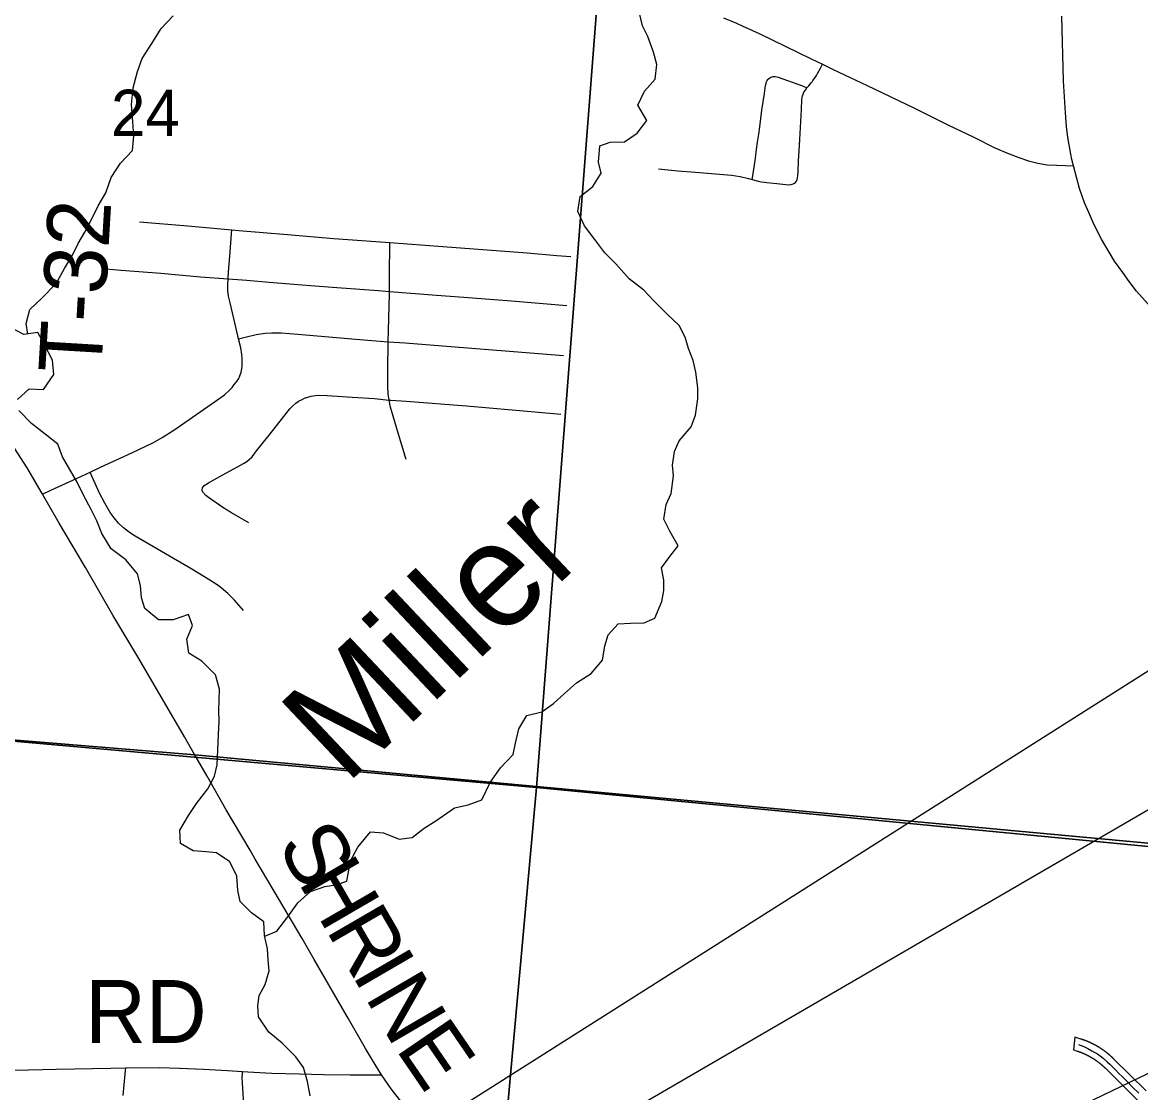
# Model space of a CAD drawing. Extents: x 0 to 34, y 0 to 22.
# Drawn here: x 5.803 to 6.814, y 18.991 to 19.958 of the extents above; entities that cross this region are included whole.
import ezdxf

# ---------------------------------------------------------------- set-up
doc = ezdxf.new("R2010")
doc.units = 0
for name, color, linetype in [('GM_X_City_Street', 7, 'Continuous'), ('GM_X_County_Road', 7, 'Continuous'), ('GM_X_County_Road_Text', 7, 'Continuous'), ('GM_X_Minor_River', 7, 'Continuous'), ('GM_X_Minor_River_Text', 7, 'Continuous'), ('GM_X_Section', 7, 'Continuous'), ('GM_X_Section_Text', 7, 'Continuous'), ('GM_X_State_Route', 7, 'Continuous'), ('GM_X_Township_Road', 7, 'Continuous'), ('GM_X_Township_Road_Text', 7, 'Continuous'), ('SC_Shading1', 7, 'Continuous'), ('SH_Text', 7, 'Continuous')]:
    doc.layers.add(name, color=color, linetype=linetype)

msp = doc.modelspace()

# ---------------------------------------------------------------- linework, layer by layer
at = {"layer": 'GM_X_City_Street'}
for points in [[(3.2709, 19.533), (4.2098, 19.4463), (4.8058, 19.3935), (5.2204, 19.3568), (5.9589, 19.2964), (6.8431, 19.2142)], [(6.8431, 19.2142), (5.9589, 19.2964), (5.2204, 19.3568), (5.2191, 19.3417), (5.2164, 19.3114), (5.2133, 19.2734), (5.2108, 19.2453), (5.2093, 19.2272), (5.2077, 19.2098), (5.2042, 19.1724), (5.2034, 19.1643), (5.2004, 19.1272), (5.1954, 19.0684), (5.1927, 19.0376), (5.1894, 18.9945), (5.185, 18.9419)]]:
    msp.add_lwpolyline(points, dxfattribs=at)
at = {"layer": 'GM_X_County_Road'}
for points in [[(5.8211, 19.5319), (5.8207, 19.5326), (5.8071, 19.5556), (5.793, 19.5776), (5.7836, 19.5916), (5.7767, 19.6008), (5.7707, 19.6081)], [(5.9586, 19.2967), (5.9495, 19.3125), (5.9083, 19.3835), (5.8848, 19.4226), (5.86, 19.4657), (5.8362, 19.5057), (5.8211, 19.5319)], [(6.1275, 19.0072), (6.1195, 19.0202), (6.1132, 19.0309), (6.0976, 19.0577), (6.0667, 19.1114), (6.0558, 19.1302), (6.0306, 19.1731), (6.0133, 19.202), (6.0087, 19.21), (5.9872, 19.2467), (5.9699, 19.2771), (5.9591, 19.2958), (5.9586, 19.2967)], [(6.2507, 18.8942), (6.2289, 18.9088), (6.2115, 18.9212), (6.2062, 18.9247), (6.2013, 18.9285), (6.1917, 18.9363), (6.1799, 18.9464), (6.1731, 18.9527), (6.162, 18.9634), (6.1536, 18.9725), (6.1458, 18.9821), (6.1364, 18.9944), (6.1275, 19.0072)]]:
    msp.add_lwpolyline(points, dxfattribs=at)
at = {"layer": 'GM_X_Minor_River'}
for points in [[(6.1768, 19.2366), (6.1935, 19.2484), (6.206, 19.251), (6.2181, 19.2555), (6.2258, 19.2714), (6.235, 19.2846), (6.2465, 19.2966), (6.2488, 19.3069), (6.2516, 19.3198), (6.2588, 19.3319), (6.2725, 19.3352), (6.2831, 19.3427), (6.293, 19.3517), (6.3037, 19.3615), (6.317, 19.3698), (6.3273, 19.3818), (6.3293, 19.3947), (6.3324, 19.4046), (6.3416, 19.4148), (6.3525, 19.4154), (6.365, 19.4157), (6.3745, 19.4198), (6.3811, 19.435), (6.3827, 19.4448), (6.3827, 19.4543), (6.3806, 19.4653), (6.3882, 19.4755), (6.3958, 19.4853), (6.3884, 19.4979), (6.3828, 19.5093), (6.3848, 19.5226), (6.3894, 19.5324), (6.3914, 19.5484), (6.3907, 19.5582), (6.3923, 19.5704), (6.3966, 19.5802), (6.4076, 19.5926), (6.4115, 19.6032), (6.4135, 19.618), (6.4136, 19.6279), (6.4118, 19.642), (6.4092, 19.6526), (6.4052, 19.6636), (6.4022, 19.6739), (6.3966, 19.6842), (6.3857, 19.6945), (6.3737, 19.7067), (6.3647, 19.7163), (6.3515, 19.7266), (6.3395, 19.74), (6.3294, 19.7499), (6.3204, 19.7621), (6.3111, 19.7744), (6.3051, 19.7873), (6.3071, 19.8009), (6.3185, 19.81), (6.3262, 19.8221), (6.3236, 19.8319), (6.3249, 19.8467), (6.3343, 19.8501), (6.3472, 19.8503), (6.3586, 19.8582), (6.3674, 19.8696), (6.3592, 19.8836), (6.3653, 19.8961), (6.3749, 19.9071), (6.3765, 19.9203), (6.3735, 19.9313), (6.3684, 19.9454), (6.3635, 19.9553), (6.3606, 19.9679)], [(5.8078, 19.6766), (5.8063, 19.686), (5.8095, 19.6989), (5.8206, 19.709), (5.8333, 19.7222), (5.8411, 19.7358), (5.8485, 19.7486), (5.8532, 19.7584), (5.8594, 19.7686), (5.8648, 19.7788), (5.8714, 19.7924), (5.8784, 19.8041), (5.8831, 19.8181), (5.8917, 19.8309), (5.9024, 19.8426), (5.9037, 19.8558), (5.9028, 19.8684), (5.9014, 19.884), (5.9031, 19.8992), (5.9071, 19.9139), (5.9111, 19.9257), (5.92, 19.9392), (5.9285, 19.9528), (5.9393, 19.9641)], [(5.7986, 19.6173), (5.809, 19.6271), (5.8219, 19.6265), (5.8312, 19.6401), (5.8302, 19.653), (5.8224, 19.668), (5.8168, 19.6779), (5.8043, 19.6762), (5.7914, 19.6828)], [(5.9107, 19.4381), (5.9097, 19.4492), (5.9071, 19.4598), (5.8963, 19.4725), (5.8831, 19.4826), (5.8746, 19.4963), (5.8701, 19.5078), (5.8653, 19.5173), (5.8579, 19.5315), (5.8523, 19.5426), (5.8457, 19.5541), (5.8393, 19.5655), (5.8349, 19.577), (5.8236, 19.5862), (5.8112, 19.5959), (5.7996, 19.6074)], [(6.063, 18.9881), (6.0605, 19.0011), (6.0569, 19.0137), (6.0501, 19.0233), (6.0378, 19.0356), (6.0257, 19.0456), (6.0164, 19.0594), (6.0158, 19.0693), (6.017, 19.0788), (6.0225, 19.0886), (6.0261, 19.1011), (6.025, 19.111), (6.0244, 19.1209), (6.0219, 19.1331), (6.0213, 19.1453), (6.01, 19.1534), (5.9999, 19.1638), (5.9977, 19.1737), (5.9968, 19.1866), (5.9905, 19.1996), (5.9784, 19.2077), (5.9689, 19.2086), (5.9572, 19.2095), (5.9458, 19.2161), (5.9452, 19.2283), (5.953, 19.2415), (5.9604, 19.2524), (5.9704, 19.2656), (5.9766, 19.277), (5.979, 19.2872), (5.9801, 19.3145), (5.9807, 19.3267), (5.9804, 19.3362), (5.9809, 19.3461), (5.981, 19.3556), (5.9774, 19.3686), (5.965, 19.3809), (5.9533, 19.3882), (5.9516, 19.4008), (5.9567, 19.4133), (5.953, 19.4232), (5.9393, 19.4184), (5.926, 19.4182), (5.9136, 19.4286), (5.9107, 19.4381)], [(6.0221, 19.1324), (6.033, 19.1368), (6.043, 19.15), (6.0519, 19.1624), (6.0634, 19.1729), (6.0764, 19.1773), (6.0867, 19.1787), (6.0962, 19.182), (6.0995, 19.2006), (6.1061, 19.2127), (6.1177, 19.2266), (6.1294, 19.2257), (6.1434, 19.2202), (6.1552, 19.2216), (6.166, 19.2299), (6.1768, 19.2366)]]:
    msp.add_lwpolyline(points, dxfattribs=at)
at = {"layer": 'GM_X_Section'}
for points in [[(5.3135, 20.3557), (6.3446, 20.2616), (6.2677, 19.2667), (5.2197, 19.3596)], [(7.3544, 20.1697), (7.2676, 19.1705), (6.2677, 19.2667), (6.3446, 20.2616)], [(5.2197, 19.3596), (6.2677, 19.2667), (6.1771, 18.2641), (5.133, 18.3597)], [(6.2677, 19.2667), (7.2676, 19.1705), (7.1751, 18.1682), (6.1771, 18.2641)]]:
    msp.add_lwpolyline(points, close=True, dxfattribs=at)
at = {"layer": 'GM_X_State_Route'}
for points in [[(6.7517, 19.8344), (6.7506, 19.8393), (6.7481, 19.8543), (6.7468, 19.8641), (6.7458, 19.8766), (6.744, 19.9054), (6.7427, 19.9639)], [(6.9759, 19.5828), (6.9726, 19.5851), (6.9399, 19.6089), (6.8982, 19.64), (6.871, 19.6605), (6.8564, 19.6714), (6.8421, 19.6832), (6.8319, 19.6924), (6.8206, 19.7035), (6.8102, 19.7153), (6.8033, 19.7242), (6.7976, 19.7323), (6.7903, 19.7426), (6.7853, 19.7506), (6.7785, 19.7623), (6.7714, 19.7759), (6.7669, 19.7865), (6.7632, 19.7952), (6.7586, 19.8083), (6.7531, 19.8286), (6.7517, 19.8344)]]:
    msp.add_lwpolyline(points, dxfattribs=at)
at = {"layer": 'GM_X_Township_Road'}
for points in [[(6.4366, 19.9625), (6.4484, 19.9576), (6.4537, 19.9553), (6.469, 19.9482), (6.516, 19.9254), (6.5262, 19.9204)], [(6.5122, 19.899), (6.5139, 19.901), (6.516, 19.9036), (6.5169, 19.9046), (6.5176, 19.9057), (6.5195, 19.9084), (6.5207, 19.9104), (6.5218, 19.9121), (6.5243, 19.9169), (6.5262, 19.9204)], [(6.5262, 19.9204), (6.5359, 19.9157), (6.5666, 19.9012), (6.6087, 19.881), (6.6401, 19.8655), (6.6631, 19.8545), (6.682, 19.845)], [(6.4626, 19.8164), (6.4631, 19.8197), (6.4643, 19.8274), (6.4655, 19.8356), (6.4666, 19.8435), (6.4675, 19.85), (6.4686, 19.8573), (6.4695, 19.864), (6.4715, 19.8791), (6.4738, 19.894), (6.4748, 19.9013), (6.4752, 19.903), (6.4754, 19.9041), (6.4758, 19.9052), (6.4763, 19.9059), (6.4768, 19.9066), (6.4774, 19.9073), (6.4786, 19.9082), (6.4799, 19.9089), (6.4816, 19.9093), (6.4833, 19.9094), (6.4848, 19.9092), (6.4862, 19.9089), (6.5082, 19.9008), (6.5122, 19.899)], [(6.4626, 19.8164), (6.468, 19.8149), (6.4711, 19.8141), (6.4758, 19.8135), (6.4849, 19.8126), (6.4957, 19.8116), (6.4978, 19.8118), (6.4997, 19.8123), (6.501, 19.8129), (6.5019, 19.8136), (6.5027, 19.8148), (6.5032, 19.8162), (6.5036, 19.8178), (6.5038, 19.8196), (6.5041, 19.8235), (6.5046, 19.8331), (6.5051, 19.8422), (6.5056, 19.8525), (6.5072, 19.8797), (6.5076, 19.8885), (6.5078, 19.8903), (6.508, 19.8919), (6.5086, 19.8935), (6.5093, 19.8951), (6.5107, 19.8971), (6.5122, 19.899)], [(6.682, 19.845), (6.6949, 19.8394), (6.7036, 19.8361), (6.7124, 19.8332), (6.721, 19.8309), (6.7292, 19.8296), (6.738, 19.8291), (6.7531, 19.8286)], [(6.3779, 19.826), (6.3955, 19.8242), (6.4115, 19.8228), (6.4438, 19.8201), (6.4518, 19.8191), (6.4594, 19.8173), (6.4626, 19.8164)], [(5.9087, 19.7781), (5.9524, 19.7743), (5.9922, 19.7707)], [(5.9888, 19.7264), (5.9893, 19.7328), (5.9904, 19.747), (5.9919, 19.7672), (5.9922, 19.7707)], [(5.9922, 19.7707), (5.9985, 19.7702), (6.0426, 19.7666), (6.0846, 19.7631), (6.135, 19.7592)], [(6.1349, 19.715), (6.1349, 19.7326), (6.135, 19.7557), (6.135, 19.7592)], [(6.135, 19.7592), (6.1829, 19.7557), (6.211, 19.7536), (6.2592, 19.75), (6.286, 19.7475), (6.2986, 19.7466)], [(5.8782, 19.7354), (5.8921, 19.7342), (5.9281, 19.7315), (5.964, 19.7283), (5.9888, 19.7264)], [(5.9984, 19.6722), (5.9963, 19.6816), (5.9906, 19.7047), (5.9893, 19.7108), (5.9885, 19.716), (5.9885, 19.7211), (5.9888, 19.7264)], [(5.9888, 19.7264), (6.0059, 19.7252), (6.0259, 19.7236), (6.0484, 19.7218), (6.0635, 19.7206), (6.0873, 19.7188), (6.1247, 19.7159), (6.1349, 19.715)], [(6.1335, 19.6697), (6.1339, 19.6799), (6.1347, 19.7126), (6.1349, 19.715)], [(6.1349, 19.715), (6.1772, 19.7116), (6.2021, 19.7098), (6.245, 19.7065), (6.2952, 19.7024)], [(5.9984, 19.6722), (6.0044, 19.6737), (6.0142, 19.6761), (6.0223, 19.6775), (6.0283, 19.6778), (6.0369, 19.6776), (6.0518, 19.6766), (6.1043, 19.672), (6.1335, 19.6697)], [(5.8642, 19.5518), (5.8736, 19.5563), (5.9017, 19.5692), (5.9214, 19.5785), (5.9294, 19.583), (5.9399, 19.5897), (5.9805, 19.6179), (5.9855, 19.6217), (5.9901, 19.626), (5.9924, 19.6282), (5.9945, 19.6309), (5.9965, 19.6333), (5.9985, 19.6363), (5.9996, 19.6389), (6.0008, 19.642), (6.0014, 19.6451), (6.0016, 19.6479), (6.0016, 19.6515), (6.0016, 19.6545), (6.0013, 19.6581), (6.0003, 19.664), (5.9984, 19.6722)], [(6.1344, 19.6169), (6.1335, 19.6227), (6.1332, 19.6294), (6.1332, 19.644), (6.1335, 19.6697)], [(6.1335, 19.6697), (6.149, 19.6686), (6.1977, 19.6648), (6.2507, 19.6604), (6.2921, 19.6571)], [(6.0075, 19.5061), (5.992, 19.515), (5.984, 19.5199), (5.9712, 19.5289), (5.9686, 19.5308), (5.9659, 19.5338), (5.9655, 19.5353), (5.9658, 19.5375), (5.9673, 19.5398), (5.9711, 19.5422), (5.9835, 19.549), (5.9973, 19.5567), (6.0027, 19.5596), (6.0059, 19.5614), (6.0082, 19.5634), (6.0105, 19.5657), (6.0146, 19.571), (6.0259, 19.5851), (6.038, 19.6007), (6.0446, 19.6089), (6.0474, 19.6118), (6.0502, 19.6141), (6.0526, 19.6158), (6.0551, 19.6172), (6.0579, 19.6185), (6.061, 19.6197), (6.0641, 19.6204), (6.0676, 19.621), (6.0707, 19.6213), (6.0784, 19.6212), (6.1009, 19.6195), (6.1211, 19.6182), (6.1344, 19.6169)], [(6.1344, 19.6169), (6.1361, 19.6168), (6.1498, 19.6159), (6.2044, 19.6117), (6.2661, 19.6062), (6.2898, 19.6043)], [(6.1498, 19.5632), (6.1419, 19.589), (6.1357, 19.6105), (6.1344, 19.6169)], [(5.8211, 19.5319), (5.8287, 19.5354), (5.8484, 19.5444), (5.8642, 19.5518)], [(6.0029, 19.4267), (5.9946, 19.4361), (5.9885, 19.4421), (5.9808, 19.4486), (5.9724, 19.4542), (5.9562, 19.464), (5.9049, 19.494), (5.8998, 19.4973), (5.8942, 19.5014), (5.8898, 19.5057), (5.8858, 19.5104), (5.8822, 19.5154), (5.8774, 19.5238), (5.873, 19.5321), (5.8658, 19.5481), (5.8642, 19.5518)], [(6.7576, 19.0346), (6.7624, 19.0326), (6.7661, 19.0308), (6.7696, 19.0289), (6.7724, 19.0273), (6.7747, 19.026), (6.7773, 19.0242), (6.78, 19.0221), (6.7837, 19.0189), (6.786, 19.0168), (6.7885, 19.0142), (6.7914, 19.0112), (6.7942, 19.0084), (6.7973, 19.0052), (6.801, 19.0015), (6.8064, 18.996), (6.8121, 18.9906)], [(5.7589, 19.0107), (5.7774, 19.011), (5.796, 19.0114), (5.8333, 19.0121), (5.883, 19.0132), (5.896, 19.0133)], [(5.896, 19.0133), (5.8958, 19.0111), (5.8938, 18.9885)], [(5.896, 19.0133), (5.9264, 19.0137), (5.945, 19.0132), (5.9666, 19.0123), (5.9882, 19.011), (6.0018, 19.0101), (6.0068, 19.0098), (6.0285, 19.0087), (6.0534, 19.0079), (6.0751, 19.0074), (6.0993, 19.0072), (6.1235, 19.0072), (6.1275, 19.0072)], [(6.0033, 18.9752), (6.0018, 18.9997), (6.0017, 19.0046), (6.0018, 19.0087), (6.0018, 19.0101)]]:
    msp.add_lwpolyline(points, dxfattribs=at)
at = {"layer": 'SC_Shading1'}
msp.add_lwpolyline([(6.8188, 18.9925), (6.804, 19.0072), (6.7896, 19.0213), (6.7897, 19.0213), (6.7895, 19.0214), (6.7894, 19.0216), (6.7893, 19.0217), (6.7891, 19.0218), (6.789, 19.022), (6.7889, 19.0221), (6.7888, 19.0222), (6.7886, 19.0223), (6.7885, 19.0225), (6.7884, 19.0226), (6.7882, 19.0227), (6.7881, 19.0228), (6.788, 19.0229), (6.7878, 19.0231), (6.7877, 19.0232), (6.7876, 19.0233), (6.7874, 19.0234), (6.7873, 19.0236), (6.7872, 19.0237), (6.787, 19.0238), (6.7869, 19.0239), (6.7868, 19.024), (6.7866, 19.0242), (6.7865, 19.0243), (6.7864, 19.0244), (6.7862, 19.0245), (6.7861, 19.0246), (6.7859, 19.0248), (6.7858, 19.0249), (6.7857, 19.025), (6.7855, 19.0251), (6.7854, 19.0252), (6.7853, 19.0253), (6.7851, 19.0255), (6.785, 19.0256), (6.7848, 19.0257), (6.7847, 19.0258), (6.7846, 19.0259), (6.7844, 19.026), (6.7843, 19.0261), (6.7841, 19.0263), (6.784, 19.0264), (6.7839, 19.0265), (6.7837, 19.0266), (6.7836, 19.0267), (6.7834, 19.0268), (6.7833, 19.0269), (6.7831, 19.0271), (6.783, 19.0272), (6.7829, 19.0273), (6.7827, 19.0274), (6.7826, 19.0275), (6.7824, 19.0276), (6.7823, 19.0277), (6.7821, 19.0278), (6.782, 19.0279), (6.7819, 19.028), (6.7817, 19.0281), (6.7816, 19.0283), (6.7814, 19.0284), (6.7813, 19.0285), (6.7811, 19.0286), (6.781, 19.0287), (6.7808, 19.0288), (6.7807, 19.0289), (6.7805, 19.029), (6.7804, 19.0291), (6.7802, 19.0292), (6.7801, 19.0293), (6.7799, 19.0294), (6.7798, 19.0295), (6.7797, 19.0296), (6.7795, 19.0297), (6.7794, 19.0298), (6.7792, 19.0299), (6.7791, 19.03), (6.7789, 19.0301), (6.7788, 19.0302), (6.7786, 19.0303), (6.7785, 19.0304), (6.7783, 19.0305), (6.7782, 19.0306), (6.778, 19.0307), (6.7779, 19.0308), (6.7777, 19.0309), (6.7775, 19.031), (6.7774, 19.0311), (6.7772, 19.0312), (6.7771, 19.0313), (6.7769, 19.0314), (6.7768, 19.0315), (6.7766, 19.0316), (6.7765, 19.0317), (6.7763, 19.0318), (6.7762, 19.0319), (6.776, 19.032), (6.7759, 19.0321), (6.7757, 19.0322), (6.7756, 19.0323), (6.7754, 19.0324), (6.7752, 19.0325), (6.7751, 19.0326), (6.7749, 19.0326), (6.7748, 19.0327), (6.7746, 19.0328), (6.7745, 19.0329), (6.7743, 19.033), (6.7741, 19.0331), (6.774, 19.0332), (6.7738, 19.0333), (6.7737, 19.0334), (6.7735, 19.0335), (6.7734, 19.0335), (6.7732, 19.0336), (6.773, 19.0337), (6.7729, 19.0338), (6.7727, 19.0339), (6.7726, 19.034), (6.7724, 19.0341), (6.7722, 19.0342), (6.7721, 19.0342), (6.7721, 19.0342), (6.7719, 19.0343), (6.7718, 19.0344), (6.7716, 19.0345), (6.7714, 19.0346), (6.7713, 19.0347), (6.7711, 19.0348), (6.7709, 19.0348), (6.7708, 19.0349), (6.7706, 19.035), (6.7704, 19.0351), (6.7702, 19.0352), (6.7701, 19.0353), (6.7699, 19.0354), (6.7697, 19.0354), (6.7696, 19.0355), (6.7694, 19.0356), (6.7692, 19.0357), (6.7691, 19.0358), (6.7689, 19.0358), (6.7687, 19.0359), (6.7686, 19.036), (6.7684, 19.0361), (6.7682, 19.0362), (6.768, 19.0362), (6.7679, 19.0363), (6.7677, 19.0364), (6.7675, 19.0365), (6.7674, 19.0365), (6.7672, 19.0366), (6.767, 19.0367), (6.7668, 19.0368), (6.7667, 19.0368), (6.7665, 19.0369), (6.7663, 19.037), (6.7661, 19.0371), (6.766, 19.0371), (6.7658, 19.0372), (6.7656, 19.0373), (6.7654, 19.0374), (6.7653, 19.0374), (6.7651, 19.0375), (6.7649, 19.0376), (6.7648, 19.0376), (6.7646, 19.0377), (6.7644, 19.0378), (6.7642, 19.0379), (6.7641, 19.0379), (6.7639, 19.038), (6.7637, 19.0381), (6.7635, 19.0381), (6.7633, 19.0382), (6.7632, 19.0383), (6.763, 19.0383), (6.7628, 19.0384), (6.7626, 19.0384), (6.7625, 19.0385), (6.7623, 19.0386), (6.7621, 19.0386), (6.7619, 19.0387), (6.7618, 19.0388), (6.7616, 19.0388), (6.7614, 19.0389), (6.7612, 19.039), (6.761, 19.039), (6.7609, 19.0391), (6.7607, 19.0391), (6.7605, 19.0392), (6.7603, 19.0393), (6.7602, 19.0393), (6.76, 19.0394), (6.7598, 19.0394), (6.7542, 19.0412), (6.7537, 19.0354), (6.7531, 19.0296), (6.7563, 19.0286), (6.7563, 19.0286), (6.7565, 19.0285), (6.7567, 19.0285), (6.7569, 19.0284), (6.757, 19.0284), (6.7572, 19.0283), (6.7574, 19.0283), (6.7576, 19.0282), (6.7577, 19.0281), (6.7579, 19.0281), (6.7581, 19.028), (6.7583, 19.0279), (6.7584, 19.0279), (6.7586, 19.0278), (6.7588, 19.0278), (6.759, 19.0277), (6.7591, 19.0276), (6.7593, 19.0276), (6.7595, 19.0275), (6.7597, 19.0274), (6.7598, 19.0274), (6.76, 19.0273), (6.7602, 19.0272), (6.7604, 19.0272), (6.7605, 19.0271), (6.7607, 19.027), (6.7609, 19.027), (6.761, 19.0269), (6.7612, 19.0268), (6.7614, 19.0267), (6.7616, 19.0267), (6.7617, 19.0266), (6.7618, 19.0266), (6.7619, 19.0265), (6.7621, 19.0265), (6.7622, 19.0264), (6.7624, 19.0263), (6.7626, 19.0262), (6.7627, 19.0262), (6.7629, 19.0261), (6.7631, 19.026), (6.7633, 19.0259), (6.7634, 19.0259), (6.7636, 19.0258), (6.7638, 19.0257), (6.7639, 19.0256), (6.7641, 19.0255), (6.7643, 19.0255), (6.7644, 19.0254), (6.7646, 19.0253), (6.7648, 19.0252), (6.7649, 19.0251), (6.7651, 19.0251), (6.7653, 19.025), (6.7654, 19.0249), (6.7656, 19.0248), (6.7658, 19.0247), (6.7659, 19.0246), (6.7661, 19.0246), (6.7663, 19.0245), (6.7664, 19.0244), (6.7666, 19.0243), (6.7668, 19.0242), (6.7669, 19.0241), (6.7671, 19.024), (6.7672, 19.0239), (6.7674, 19.0239), (6.7676, 19.0238), (6.7677, 19.0237), (6.7679, 19.0236), (6.7681, 19.0235), (6.7682, 19.0234), (6.7684, 19.0233), (6.7685, 19.0232), (6.7687, 19.0231), (6.7689, 19.023), (6.769, 19.0229), (6.7692, 19.0228), (6.7693, 19.0228), (6.7695, 19.0227), (6.7697, 19.0226), (6.7698, 19.0225), (6.77, 19.0224), (6.7701, 19.0223), (6.7703, 19.0222), (6.7705, 19.0221), (6.7706, 19.022), (6.7708, 19.0219), (6.7709, 19.0218), (6.7711, 19.0217), (6.7712, 19.0216), (6.7714, 19.0215), (6.7716, 19.0214), (6.7717, 19.0213), (6.7719, 19.0212), (6.772, 19.0211), (6.7722, 19.021), (6.7723, 19.0209), (6.7725, 19.0208), (6.7726, 19.0207), (6.7728, 19.0206), (6.7729, 19.0205), (6.7731, 19.0203), (6.7732, 19.0202), (6.7734, 19.0201), (6.7736, 19.02), (6.7737, 19.0199), (6.7739, 19.0198), (6.774, 19.0197), (6.7742, 19.0196), (6.7743, 19.0195), (6.7745, 19.0194), (6.7746, 19.0193), (6.7748, 19.0192), (6.7749, 19.019), (6.7751, 19.0189), (6.7752, 19.0188), (6.7754, 19.0187), (6.7755, 19.0186), (6.7756, 19.0185), (6.7758, 19.0184), (6.7759, 19.0183), (6.7761, 19.0181), (6.7762, 19.018), (6.7764, 19.0179), (6.7765, 19.0178), (6.7767, 19.0177), (6.7768, 19.0176), (6.7769, 19.0175), (6.777, 19.0174), (6.7771, 19.0173), (6.7772, 19.0173), (6.7773, 19.0172), (6.7774, 19.0171), (6.7775, 19.017), (6.7776, 19.0169), (6.7777, 19.0169), (6.7778, 19.0168), (6.7779, 19.0167), (6.778, 19.0166), (6.7781, 19.0165), (6.7782, 19.0165), (6.7783, 19.0164), (6.7783, 19.0163), (6.7784, 19.0162), (6.7785, 19.0161), (6.7786, 19.016), (6.7787, 19.016), (6.7788, 19.0159), (6.7789, 19.0158), (6.779, 19.0157), (6.7791, 19.0156), (6.7792, 19.0156), (6.7793, 19.0155), (6.7794, 19.0154), (6.7795, 19.0153), (6.7796, 19.0152), (6.7797, 19.0151), (6.7797, 19.015), (6.7798, 19.015), (6.7799, 19.0149), (6.78, 19.0148), (6.7801, 19.0147), (6.7802, 19.0146), (6.7803, 19.0145), (6.7804, 19.0145), (6.7805, 19.0144), (6.7806, 19.0143), (6.7807, 19.0142), (6.7807, 19.0141), (6.7808, 19.014), (6.7809, 19.0139), (6.781, 19.0139), (6.7811, 19.0138), (6.7812, 19.0137), (6.7813, 19.0136), (6.7814, 19.0135), (6.7815, 19.0134), (6.7816, 19.0133), (6.8025, 18.9926), (6.8025, 18.9926), (6.8026, 18.9926), (6.8026, 18.9926), (6.8132, 18.982)], dxfattribs=at)
at = {"layer": 'SH_Text'}
for points in [[(9.2218, 20.8941), (4.458, 17.8745), (9.2218, 20.6417)], [(9.2453, 20.175), (4.4659, 17.8756), (9.2453, 19.8796)]]:
    msp.add_lwpolyline(points, close=True, dxfattribs=at)

# ---------------------------------------------------------------- texts
at = {"layer": 'GM_X_County_Road_Text'}
for s, rotation, p in [('S', 300.135, (6.0324, 19.2147)), ('H', 300.1335, (6.0517, 19.1815)), ('R', 300.1322, (6.0768, 19.1383)), ('I', 300.1439, (6.1002, 19.0979)), ('N', 300.2948, (6.112, 19.0776)), ('E', 304.3702, (6.1396, 19.0307))]:
    msp.add_text(s, height=0.0568, rotation=rotation, dxfattribs=at).set_placement(p)
at = {"layer": 'GM_X_Minor_River_Text'}
msp.add_text('Miller', height=0.09475, rotation=43.3539, dxfattribs=at).set_placement((6.095, 19.2682))
at = {"layer": 'GM_X_Section_Text'}
msp.add_text('24', height=0.04186, rotation=0, dxfattribs=at).set_placement((5.883, 19.8556))
at = {"layer": 'GM_X_Township_Road_Text'}
for s, rotation, p in [('T-32', 86.5979, (5.874, 19.64)), ('RD', 0, (5.8597, 19.0359))]:
    msp.add_text(s, height=0.05682, rotation=rotation, dxfattribs=at).set_placement(p)

doc.saveas('drawing.dxf')
